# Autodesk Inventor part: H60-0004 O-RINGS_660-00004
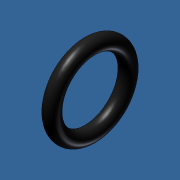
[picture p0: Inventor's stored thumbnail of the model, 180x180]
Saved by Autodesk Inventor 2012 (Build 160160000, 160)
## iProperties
Created: 2013-10
Part Number: H60-0004 O-RINGS_660-00004
Material: Default
Document SubType Name: Modeling
Designer: Admin
Density: 1 g/cm^3
Author: Admin
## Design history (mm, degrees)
node "H60-0004 O-RINGS_660-000041"
node "Base1"
body "Solid1"
